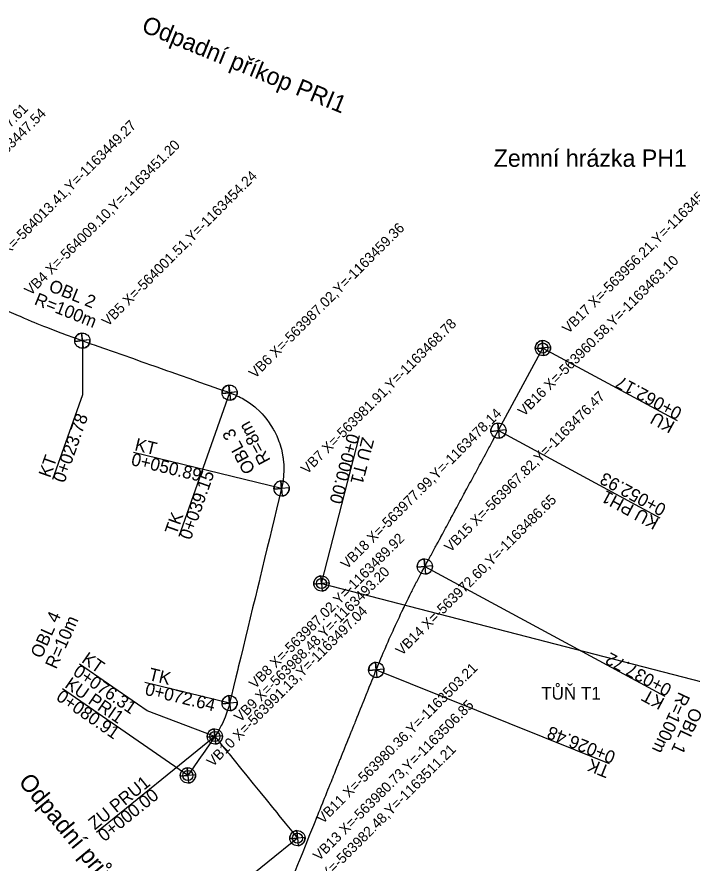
# Model space of a CAD drawing. Extents: x -564052 to -563798, y -1163587 to -1163361.
# Drawn here: x -564007.9 to -563941.5, y -1163505.7 to -1163422.4 of the extents above; entities that cross this region are included whole.
import ezdxf

# ---------------------------------------------------------------- set-up
doc = ezdxf.new("R2010")
doc.units = 0
for name, color, linetype in [('4', 7, 'Continuous'), ('5', 7, 'Continuous'), ('_popis staničení PH1', 7, 'Continuous'), ('_popis staničení PRI1', 7, 'Continuous'), ('_popis staničení PRU1', 7, 'Continuous'), ('_popis staničení T1', 7, 'Continuous'), ('_rám C35', 7, 'Continuous'), ('Default', 7, 'Continuous')]:
    doc.layers.add(name, color=color, linetype=linetype)

msp = doc.modelspace()

# ---------------------------------------------------------------- linework, layer by layer
for points in [[(-564008.737, -1163451.365), (-564007.821, -1163451.766), (-564007.636, -1163451.846), (-564007.226, -1163452.021), (-564006.901, -1163452.158), (-564006.468, -1163452.339), (-564006.293, -1163452.411), (-564005.977, -1163452.541), (-564005.335, -1163452.8), (-564005.049, -1163452.914), (-564004.118, -1163453.278), (-564004.036, -1163453.31), (-564003.622, -1163453.468), (-564003.43, -1163453.54), (-564003.183, -1163453.633), (-564002.245, -1163453.978), (-564001.885, -1163454.108), (-564001.714, -1163454.169), (-564001.509, -1163454.241), (-564001.303, -1163454.314), (-564000.564, -1163454.575), (-564000.36, -1163454.647), (-563999.417, -1163454.981), (-563998.474, -1163455.314), (-563997.531, -1163455.647), (-563996.589, -1163455.98), (-563995.646, -1163456.314), (-563995.452, -1163456.382), (-563995.448, -1163456.384), (-563994.703, -1163456.647), (-563994.566, -1163456.696), (-563994.476, -1163456.727), (-563994.186, -1163456.83), (-563993.76, -1163456.98), (-563993.219, -1163457.172), (-563992.817, -1163457.314), (-563991.874, -1163457.647), (-563990.932, -1163457.98), (-563989.989, -1163458.313), (-563989.326, -1163458.548), (-563989.046, -1163458.647), (-563988.103, -1163458.98), (-563987.622, -1163459.15), (-563987.311, -1163459.26), (-563987.16, -1163459.313), (-563987.022, -1163459.362), (-563986.743, -1163459.467), (-563986.664, -1163459.498), (-563986.631, -1163459.512), (-563986.476, -1163459.578), (-563986.234, -1163459.689), (-563986.126, -1163459.742), (-563985.948, -1163459.833), (-563985.802, -1163459.912), (-563985.439, -1163460.127), (-563985.361, -1163460.176), (-563984.953, -1163460.456), (-563984.556, -1163460.768), (-563984.493, -1163460.821), (-563984.061, -1163461.219), (-563983.898, -1163461.385), (-563983.831, -1163461.455), (-563983.659, -1163461.647), (-563983.474, -1163461.866), (-563983.29, -1163462.103), (-563983.198, -1163462.228), (-563982.955, -1163462.585), (-563982.734, -1163462.951), (-563982.73, -1163462.956), (-563982.717, -1163462.98), (-563982.665, -1163463.074), (-563982.656, -1163463.091), (-563982.395, -1163463.617), (-563982.242, -1163463.979), (-563982.174, -1163464.161), (-563982.101, -1163464.367), (-563982.092, -1163464.395), (-563982.032, -1163464.585), (-563982.015, -1163464.641), (-563981.993, -1163464.719), (-563981.936, -1163464.931), (-563981.853, -1163465.29), (-563981.78, -1163465.696), (-563981.763, -1163465.812), (-563981.756, -1163465.869), (-563981.75, -1163465.912), (-563981.701, -1163466.453), (-563981.688, -1163466.91), (-563981.69, -1163467.04), (-563981.708, -1163467.467), (-563981.721, -1163467.627), (-563981.751, -1163467.907), (-563981.795, -1163468.209), (-563981.912, -1163468.784), (-563981.938, -1163468.889), (-563982.011, -1163469.191), (-563982.173, -1163469.861), (-563982.408, -1163470.833), (-563982.643, -1163471.805), (-563982.878, -1163472.777), (-563983.113, -1163473.749), (-563983.348, -1163474.721), (-563983.583, -1163475.693), (-563983.818, -1163476.665), (-563984.052, -1163477.637), (-563984.101, -1163477.836), (-563984.287, -1163478.609), (-563984.522, -1163479.581), (-563984.757, -1163480.553), (-563984.992, -1163481.525), (-563985.227, -1163482.497), (-563985.462, -1163483.469), (-563985.697, -1163484.441), (-563985.932, -1163485.413), (-563986.167, -1163486.385), (-563986.222, -1163486.612), (-563986.402, -1163487.357), (-563986.637, -1163488.329), (-563986.872, -1163489.301), (-563987.022, -1163489.919), (-563987.114, -1163490.272), (-563987.22, -1163490.627), (-563987.431, -1163491.219), (-563987.47, -1163491.317), (-563987.771, -1163491.988), (-563987.842, -1163492.131), (-563988.119, -1163492.635), (-563988.342, -1163492.996), (-563988.514, -1163493.254), (-563988.906, -1163493.822), (-563989.475, -1163494.644), (-563990.043, -1163495.467), (-563990.612, -1163496.29), (-563991.13, -1163497.04)], [(-563980.618, -1163506.572), (-563980.244, -1163505.644), (-563980.216, -1163505.574), (-563979.871, -1163504.716), (-563979.497, -1163503.789), (-563979.124, -1163502.861), (-563978.751, -1163501.933), (-563978.377, -1163501.006), (-563978.349, -1163500.935), (-563978.237, -1163500.657), (-563978.236, -1163500.655), (-563978.125, -1163500.38), (-563978.015, -1163500.104), (-563978.004, -1163500.078), (-563977.904, -1163499.829), (-563977.793, -1163499.554), (-563977.682, -1163499.279), (-563977.631, -1163499.15), (-563977.571, -1163499.003), (-563977.461, -1163498.728), (-563977.35, -1163498.453), (-563977.257, -1163498.223), (-563977.239, -1163498.177), (-563977.128, -1163497.902), (-563977.017, -1163497.627), (-563976.907, -1163497.351), (-563976.884, -1163497.295), (-563976.796, -1163497.076), (-563976.685, -1163496.801), (-563976.574, -1163496.525), (-563976.511, -1163496.367), (-563976.463, -1163496.25), (-563976.353, -1163495.975), (-563976.242, -1163495.699), (-563976.137, -1163495.44), (-563976.131, -1163495.424), (-563976.02, -1163495.149), (-563975.909, -1163494.873), (-563975.798, -1163494.598), (-563975.764, -1163494.512), (-563975.688, -1163494.323), (-563975.577, -1163494.047), (-563975.466, -1163493.772), (-563975.39, -1163493.584), (-563975.355, -1163493.497), (-563975.244, -1163493.221), (-563975.134, -1163492.946), (-563975.023, -1163492.671), (-563975.017, -1163492.657), (-563974.912, -1163492.395), (-563974.801, -1163492.12), (-563974.69, -1163491.845), (-563974.644, -1163491.729), (-563974.58, -1163491.569), (-563974.469, -1163491.294), (-563974.358, -1163491.019), (-563974.27, -1163490.801), (-563974.247, -1163490.744), (-563974.136, -1163490.468), (-563974.025, -1163490.193), (-563973.915, -1163489.918), (-563973.897, -1163489.873), (-563973.804, -1163489.642), (-563973.693, -1163489.367), (-563973.582, -1163489.092), (-563973.524, -1163488.946), (-563973.471, -1163488.816), (-563973.361, -1163488.541), (-563973.25, -1163488.266), (-563973.15, -1163488.018), (-563973.139, -1163487.99), (-563973.028, -1163487.715), (-563972.917, -1163487.44), (-563972.807, -1163487.164), (-563972.777, -1163487.09), (-563972.696, -1163486.889), (-563972.599, -1163486.649), (-563972.585, -1163486.614), (-563972.474, -1163486.339), (-563972.402, -1163486.163), (-563972.361, -1163486.064), (-563972.249, -1163485.789), (-563972.135, -1163485.515), (-563972.02, -1163485.241), (-563972.019, -1163485.239), (-563971.905, -1163484.968), (-563971.789, -1163484.695), (-563971.736, -1163484.572), (-563971.672, -1163484.422), (-563971.627, -1163484.32), (-563971.554, -1163484.15), (-563971.435, -1163483.878), (-563971.316, -1163483.606), (-563971.226, -1163483.404), (-563971.195, -1163483.335), (-563971.074, -1163483.064), (-563970.952, -1163482.793), (-563970.83, -1163482.523), (-563970.826, -1163482.515), (-563970.816, -1163482.492), (-563970.706, -1163482.253), (-563970.582, -1163481.983), (-563970.457, -1163481.714), (-563970.396, -1163481.584), (-563970.331, -1163481.446), (-563970.205, -1163481.177), (-563970.077, -1163480.909), (-563969.968, -1163480.68), (-563969.949, -1163480.641), (-563969.87, -1163480.479), (-563969.82, -1163480.374), (-563969.69, -1163480.107), (-563969.559, -1163479.841), (-563969.53, -1163479.781), (-563969.428, -1163479.575), (-563969.296, -1163479.309), (-563969.163, -1163479.044), (-563969.084, -1163478.886), (-563969.029, -1163478.779), (-563968.894, -1163478.514), (-563968.869, -1163478.464), (-563968.759, -1163478.25), (-563968.628, -1163477.996), (-563968.623, -1163477.986), (-563968.486, -1163477.723), (-563968.348, -1163477.46), (-563968.21, -1163477.198), (-563968.164, -1163477.111), (-563968.071, -1163476.936), (-563967.931, -1163476.674), (-563967.823, -1163476.473), (-563967.79, -1163476.413), (-563967.691, -1163476.229), (-563967.649, -1163476.151), (-563967.508, -1163475.89), (-563967.367, -1163475.629), (-563967.226, -1163475.368), (-563967.216, -1163475.349), (-563967.085, -1163475.107), (-563966.944, -1163474.846), (-563966.803, -1163474.585), (-563966.741, -1163474.47), (-563966.662, -1163474.323), (-563966.521, -1163474.062), (-563966.38, -1163473.801), (-563966.265, -1163473.59), (-563966.239, -1163473.54), (-563966.098, -1163473.279), (-563965.957, -1163473.018), (-563965.816, -1163472.757), (-563965.79, -1163472.71), (-563965.675, -1163472.495), (-563965.534, -1163472.234), (-563965.393, -1163471.973), (-563965.315, -1163471.83), (-563965.252, -1163471.712), (-563965.111, -1163471.451), (-563964.97, -1163471.19), (-563964.84, -1163470.95), (-563964.829, -1163470.929), (-563964.688, -1163470.667), (-563964.547, -1163470.406), (-563964.406, -1163470.145), (-563964.365, -1163470.07), (-563964.265, -1163469.884), (-563964.123, -1163469.623), (-563963.982, -1163469.362), (-563963.89, -1163469.19), (-563963.841, -1163469.1), (-563963.7, -1163468.839), (-563963.559, -1163468.578), (-563963.418, -1163468.317), (-563963.415, -1163468.31), (-563963.277, -1163468.056), (-563963.136, -1163467.795), (-563962.995, -1163467.534), (-563962.94, -1163467.43), (-563962.854, -1163467.272), (-563962.713, -1163467.011), (-563962.572, -1163466.75), (-563962.464, -1163466.55), (-563962.431, -1163466.489), (-563962.29, -1163466.228), (-563962.149, -1163465.967), (-563962.008, -1163465.706), (-563961.989, -1163465.67), (-563961.867, -1163465.444), (-563961.726, -1163465.183), (-563961.585, -1163464.922), (-563961.514, -1163464.79), (-563961.444, -1163464.661), (-563961.303, -1163464.4), (-563961.162, -1163464.139), (-563961.039, -1163463.911), (-563961.021, -1163463.878), (-563960.88, -1163463.616), (-563960.739, -1163463.355), (-563956.21, -1163454.967), (-563956.209, -1163454.966)], [(-563988.478, -1163493.203), (-563987.986, -1163493.809), (-563987.848, -1163493.98), (-563987.218, -1163494.756), (-563987.081, -1163494.925), (-563986.588, -1163495.533), (-563985.957, -1163496.309), (-563985.327, -1163497.086), (-563984.697, -1163497.863), (-563984.067, -1163498.639), (-563983.437, -1163499.416), (-563982.807, -1163500.192), (-563982.395, -1163500.7), (-563982.177, -1163500.969), (-563981.547, -1163501.745), (-563980.917, -1163502.522), (-563980.358, -1163503.212)]]:
    msp.add_lwpolyline(points)
at = {"layer": '5'}
msp.add_line((-563977.993, -1163478.142), (-563940.586, -1163487.812), dxfattribs=at)
at = {"layer": '_popis staničení PH1'}
for points in [[(-563956.209, -1163454.966), (-563943.01, -1163462.093)], [(-563960.584, -1163463.099), (-563944.707, -1163471.673)], [(-563967.823, -1163476.473), (-563944.204, -1163489.227)], [(-563972.599, -1163486.649), (-563949.695, -1163495.868)]]:
    msp.add_lwpolyline(points, dxfattribs=at)
msp.add_circle((-563956.209, -1163454.966), 0.5, dxfattribs=at)
at = {"layer": '_popis staničení PRI1'}
for points in [[(-564001.509, -1163454.241), (-564001.502, -1163459.568), (-564004.444, -1163467.892)], [(-563987.022, -1163459.362), (-563992.021, -1163473.504)], [(-563981.912, -1163468.784), (-563996.492, -1163465.26)], [(-563988.478, -1163493.203), (-563995.124, -1163490.664), (-564001.8, -1163486.071)], [(-563991.13, -1163497.04), (-564003.471, -1163488.514)], [(-563987.022, -1163489.919), (-563995.349, -1163487.906)]]:
    msp.add_lwpolyline(points, dxfattribs=at)
msp.add_circle((-563991.13, -1163497.04), 0.5, dxfattribs=at)
at = {"layer": '_popis staničení PRU1'}
for points in [[(-563988.478, -1163493.203), (-564000.126, -1163502.654)], [(-563980.358, -1163503.212), (-563992.006, -1163512.662)]]:
    msp.add_lwpolyline(points, dxfattribs=at)
for centre in [(-563988.478, -1163493.203), (-563980.358, -1163503.212)]:
    msp.add_circle(centre, 0.5, dxfattribs=at)
at = {"layer": '_popis staničení T1'}
msp.add_lwpolyline([(-563977.993, -1163478.142), (-563974.239, -1163463.619)], dxfattribs=at)
msp.add_circle((-563977.993, -1163478.142), 0.5, dxfattribs=at)
at = {"layer": '_rám C35'}
for p, q in [((-564001.509, -1163454.241), (-564001.579, -1163453.494)), ((-564001.509, -1163454.241), (-564001.579, -1163453.494)), ((-564001.578, -1163453.495), (-564001.44, -1163454.988)), ((-564000.762, -1163454.172), (-564002.256, -1163454.311)), ((-564002.256, -1163454.311), (-564001.509, -1163454.241)), ((-564002.256, -1163454.311), (-564001.509, -1163454.241)), ((-564000.762, -1163454.172), (-564001.509, -1163454.241)), ((-564001.509, -1163454.241), (-564001.439, -1163454.988)), ((-563956.209, -1163454.966), (-563956.279, -1163454.218)), ((-563956.209, -1163454.966), (-563956.279, -1163454.218)), ((-563956.278, -1163454.219), (-563956.14, -1163455.712)), ((-563955.462, -1163454.896), (-563956.956, -1163455.035)), ((-563956.956, -1163455.035), (-563956.209, -1163454.966)), ((-563956.956, -1163455.035), (-563956.209, -1163454.966)), ((-563955.462, -1163454.896), (-563956.209, -1163454.966)), ((-563956.209, -1163454.966), (-563956.139, -1163455.713)), ((-563986.276, -1163459.292), (-563987.769, -1163459.431)), ((-563987.769, -1163459.431), (-563987.022, -1163459.362)), ((-563987.769, -1163459.431), (-563987.022, -1163459.362)), ((-563987.092, -1163458.615), (-563986.953, -1163460.109)), ((-563987.022, -1163459.362), (-563987.092, -1163458.615)), ((-563987.022, -1163459.362), (-563987.092, -1163458.615)), ((-563986.275, -1163459.292), (-563987.022, -1163459.362)), ((-563987.022, -1163459.362), (-563986.953, -1163460.109)), ((-563960.584, -1163463.099), (-563960.654, -1163462.352)), ((-563960.584, -1163463.099), (-563960.654, -1163462.352)), ((-563960.654, -1163462.353), (-563960.515, -1163463.846)), ((-563961.332, -1163463.169), (-563960.584, -1163463.099)), ((-563961.332, -1163463.169), (-563960.584, -1163463.099)), ((-563959.838, -1163463.03), (-563961.331, -1163463.169)), ((-563959.837, -1163463.03), (-563960.584, -1163463.099)), ((-563960.584, -1163463.099), (-563960.515, -1163463.847)), ((-563981.912, -1163468.784), (-563981.982, -1163468.037)), ((-563981.912, -1163468.784), (-563981.982, -1163468.037)), ((-563981.982, -1163468.038), (-563981.843, -1163469.531)), ((-563982.66, -1163468.854), (-563981.912, -1163468.784)), ((-563981.166, -1163468.715), (-563982.659, -1163468.854)), ((-563982.659, -1163468.854), (-563981.912, -1163468.784)), ((-563981.165, -1163468.715), (-563981.912, -1163468.784)), ((-563981.912, -1163468.784), (-563981.843, -1163469.531)), ((-563967.823, -1163476.473), (-563967.892, -1163475.726)), ((-563967.823, -1163476.473), (-563967.892, -1163475.726)), ((-563967.892, -1163475.727), (-563967.753, -1163477.22)), ((-563968.57, -1163476.543), (-563967.823, -1163476.473)), ((-563968.57, -1163476.543), (-563967.823, -1163476.473)), ((-563967.076, -1163476.404), (-563968.569, -1163476.543)), ((-563967.075, -1163476.404), (-563967.823, -1163476.473)), ((-563967.823, -1163476.473), (-563967.753, -1163477.22)), ((-563978.063, -1163477.395), (-563977.924, -1163478.889)), ((-563977.993, -1163478.142), (-563978.063, -1163477.395)), ((-563977.993, -1163478.142), (-563978.063, -1163477.395)), ((-563977.246, -1163478.073), (-563978.74, -1163478.212)), ((-563978.74, -1163478.212), (-563977.993, -1163478.142)), ((-563978.74, -1163478.212), (-563977.993, -1163478.142)), ((-563977.246, -1163478.073), (-563977.993, -1163478.142)), ((-563977.993, -1163478.142), (-563977.923, -1163478.889)), ((-563972.599, -1163486.649), (-563972.669, -1163485.902)), ((-563972.599, -1163486.649), (-563972.669, -1163485.902)), ((-563972.669, -1163485.903), (-563972.53, -1163487.396)), ((-563971.853, -1163486.58), (-563973.346, -1163486.719)), ((-563973.346, -1163486.719), (-563972.599, -1163486.649)), ((-563973.346, -1163486.719), (-563972.599, -1163486.649)), ((-563971.852, -1163486.58), (-563972.599, -1163486.649)), ((-563972.599, -1163486.649), (-563972.53, -1163487.396)), ((-563987.022, -1163489.919), (-563987.091, -1163489.172)), ((-563987.022, -1163489.919), (-563987.091, -1163489.172)), ((-563987.091, -1163489.173), (-563986.952, -1163490.666)), ((-563987.769, -1163489.989), (-563987.022, -1163489.919)), ((-563987.769, -1163489.989), (-563987.022, -1163489.919)), ((-563986.275, -1163489.85), (-563987.768, -1163489.989)), ((-563986.274, -1163489.85), (-563987.022, -1163489.919)), ((-563987.022, -1163489.919), (-563986.952, -1163490.667)), ((-563988.478, -1163493.203), (-563988.547, -1163492.456)), ((-563988.478, -1163493.203), (-563988.547, -1163492.456)), ((-563988.547, -1163492.457), (-563988.408, -1163493.95)), ((-563989.225, -1163493.273), (-563988.478, -1163493.203)), ((-563989.225, -1163493.273), (-563988.478, -1163493.203)), ((-563987.731, -1163493.134), (-563989.224, -1163493.273)), ((-563987.73, -1163493.134), (-563988.478, -1163493.203)), ((-563988.478, -1163493.203), (-563988.408, -1163493.95)), ((-563991.13, -1163497.04), (-563991.2, -1163496.293)), ((-563991.13, -1163497.04), (-563991.2, -1163496.293)), ((-563991.199, -1163496.293), (-563991.061, -1163497.787)), ((-563990.383, -1163496.971), (-563991.877, -1163497.109)), ((-563991.877, -1163497.11), (-563991.13, -1163497.04)), ((-563991.877, -1163497.109), (-563991.13, -1163497.04)), ((-563990.383, -1163496.97), (-563991.13, -1163497.04)), ((-563991.13, -1163497.04), (-563991.06, -1163497.787)), ((-563980.358, -1163503.212), (-563980.427, -1163502.464)), ((-563980.358, -1163503.212), (-563980.427, -1163502.464)), ((-563980.427, -1163502.465), (-563980.288, -1163503.958)), ((-563981.105, -1163503.281), (-563980.358, -1163503.212)), ((-563981.105, -1163503.281), (-563980.358, -1163503.212)), ((-563979.611, -1163503.142), (-563981.104, -1163503.281)), ((-563979.611, -1163503.142), (-563980.358, -1163503.212)), ((-563980.358, -1163503.212), (-563980.288, -1163503.959))]:
    msp.add_line(p, q, dxfattribs=at)
for centre in [(-564001.509, -1163454.241), (-563956.209, -1163454.966), (-563987.022, -1163459.362), (-563960.584, -1163463.099), (-563981.912, -1163468.784), (-563967.823, -1163476.473), (-563977.993, -1163478.142), (-563972.599, -1163486.649), (-563987.022, -1163489.919), (-563988.478, -1163493.203), (-563991.13, -1163497.04), (-563980.358, -1163503.212)]:
    msp.add_circle(centre, 0.75, dxfattribs=at)
for centre, start, end in [((-564001.509, -1163454.241), 95.31679, 185.31679), ((-564001.509, -1163454.241), 95.31679, 185.31679), ((-564001.509, -1163454.241), 275.31679, 5.31679), ((-563956.209, -1163454.966), 95.31679, 185.31679), ((-563956.209, -1163454.966), 95.31679, 185.31679), ((-563956.209, -1163454.966), 275.31679, 5.31679), ((-563987.022, -1163459.362), 95.31679, 185.31679), ((-563987.022, -1163459.362), 95.31679, 185.31679), ((-563987.022, -1163459.362), 275.31679, 5.31679), ((-563960.584, -1163463.099), 95.31679, 185.31679), ((-563960.584, -1163463.099), 95.31679, 185.31679), ((-563960.584, -1163463.099), 275.31679, 5.31679), ((-563981.912, -1163468.784), 95.31679, 185.31679), ((-563981.912, -1163468.784), 95.31679, 185.31679), ((-563981.912, -1163468.784), 275.31679, 5.31679), ((-563967.823, -1163476.473), 95.31679, 185.31679), ((-563967.823, -1163476.473), 95.31679, 185.31679), ((-563967.823, -1163476.473), 275.31679, 5.31679), ((-563977.993, -1163478.142), 95.31679, 185.31679), ((-563977.993, -1163478.142), 95.31679, 185.31679), ((-563977.993, -1163478.142), 275.31679, 5.31679), ((-563972.599, -1163486.649), 95.31679, 185.31679), ((-563972.599, -1163486.649), 95.31679, 185.31679), ((-563972.599, -1163486.649), 275.31679, 5.31679), ((-563987.022, -1163489.919), 95.31679, 185.31679), ((-563987.022, -1163489.919), 95.31679, 185.31679), ((-563987.022, -1163489.919), 275.31679, 5.31679), ((-563988.478, -1163493.203), 95.31679, 185.31679), ((-563988.478, -1163493.203), 95.31679, 185.31679), ((-563988.478, -1163493.203), 275.31679, 5.31679), ((-563991.13, -1163497.04), 95.31679, 185.31679), ((-563991.13, -1163497.04), 95.31679, 185.31679), ((-563991.13, -1163497.04), 275.31679, 5.31679), ((-563980.358, -1163503.212), 95.31679, 185.31679), ((-563980.358, -1163503.212), 95.31679, 185.31679), ((-563980.358, -1163503.212), 275.31679, 5.31679)]:
    msp.add_arc(centre, 0.75, start, end, dxfattribs=at)

# ---------------------------------------------------------------- texts
at = {"layer": '4'}
for s, height, rotation, p in [('Odpadní příkop PRI1', 1.70472, 337.7031, (-563995.793, -1163423.777)), ('Zemní hrázka PH1', 1.70472, 360, (-563961.048, -1163437.127)), ('TŮŇ T1', 1.25, 360, (-563956.376, -1163489.573)), ('Odpadní průleh PRU1', 1.70472, 309.48875, (-564007.868, -1163497.695))]:
    msp.add_text(s, height=height, rotation=rotation, dxfattribs=at).set_placement(p)
at = {"layer": '_popis staničení PH1'}
for s, rotation, p in [('0+062.17', 151.63216, (-563942.416, -1163460.993)), ('KU ', 151.63216, (-563943.129, -1163462.313)), ('0+052.93', 151.63216, (-563943.971, -1163470.48)), ('KU PH1 ', 151.63216, (-563944.684, -1163471.8)), ('0+037.72', 151.63216, (-563943.427, -1163488.211)), ('KT ', 151.63216, (-563944.14, -1163489.531)), ('R=100m ', 244.85429, (-563942.815, -1163488.741)), ('OBL 1', 244.85429, (-563941.595, -1163490.259)), ('0+026.48', 158.07641, (-563948.961, -1163494.771)), ('TK ', 158.07641, (-563949.521, -1163496.163))]:
    msp.add_text(s, height=1.25, rotation=rotation, dxfattribs=at).set_placement(p)
at = {"layer": '_popis staničení PRI1'}
for s, rotation, p in [('OBL 2', 338.1901, (-564004.911, -1163449.325)), ('R=100m ', 338.1901, (-564006.322, -1163450.645)), ('0+023.78', 70.53291, (-564003.265, -1163468.309)), ('R=8m ', 118.47147, (-563982.968, -1163466.015)), ('OBL 3', 118.47147, (-563984.452, -1163466.949)), ('KT ', 346.41002, (-563996.434, -1163465.017)), ('KT ', 70.53291, (-564004.68, -1163467.809)), ('0+050.89', 346.41002, (-563996.786, -1163466.475)), ('0+039.15', 70.53291, (-563990.843, -1163473.921)), ('TK ', 70.53291, (-563992.257, -1163473.421)), ('OBL 4', 65.88483, (-564005.524, -1163485.591)), ('R=10m ', 65.88483, (-564004.078, -1163486.644)), ('KT ', 325.35964, (-564001.665, -1163485.838)), ('0+076.31', 325.35964, (-564002.518, -1163487.073)), ('TK ', 346.41002, (-563995.073, -1163487.636)), ('KU PRI1 ', 325.35964, (-564003.329, -1163488.308)), ('0+072.64', 346.41002, (-563995.426, -1163489.094)), ('0+080.91', 325.35964, (-564004.182, -1163489.542))]:
    msp.add_text(s, height=1.25, rotation=rotation, dxfattribs=at).set_placement(p)
at = {"layer": '_popis staničení PRU1'}
for s, p in [('ZU PRU1 ', (-564000.284, -1163502.46)), ('0+000.00', (-563999.339, -1163503.624))]:
    msp.add_text(s, height=1.25, rotation=39.05251, dxfattribs=at).set_placement(p)
at = {"layer": '_popis staničení T1'}
for s, p in [('0+000.00', (-563975.449, -1163463.307)), ('ZU T1 ', (-563973.997, -1163463.682))]:
    msp.add_text(s, height=1.25, rotation=255.5058, dxfattribs=at).set_placement(p)
at = {"layer": 'Default'}
for s, p in [('VB1 X=-564024.04,Y=-1163447.61', (-564021.54, -1163446.262)), ('VB2 X=-564022.49,Y=-1163447.54', (-564019.779, -1163446.729)), ('VB3 X=-564013.41,Y=-1163449.27', (-564010.91, -1163447.923)), ('VB4 X=-564009.10,Y=-1163451.20', (-564006.6, -1163449.856)), ('VB5 X=-564001.51,Y=-1163454.24', (-563999.009, -1163452.893)), ('VB17 X=-563956.21,Y=-1163454.97', (-563953.709, -1163453.617)), ('VB6 X=-563987.02,Y=-1163459.36', (-563984.523, -1163458.014)), ('VB16 X=-563960.58,Y=-1163463.10', (-563958.085, -1163461.751)), ('VB7 X=-563981.91,Y=-1163468.78', (-563979.413, -1163467.436)), ('VB15 X=-563967.82,Y=-1163476.47', (-563965.323, -1163475.125)), ('VB18 X=-563977.99,Y=-1163478.14', (-563975.493, -1163476.794)), ('VB14 X=-563972.60,Y=-1163486.65', (-563970.1, -1163485.301)), ('VB8 X=-563987.02,Y=-1163489.92', (-563984.522, -1163488.571)), ('VB9 X=-563988.48,Y=-1163493.20', (-563985.978, -1163491.855)), ('VB10 X=-563991.13,Y=-1163497.04', (-563988.692, -1163496.249)), ('VB11 X=-563980.36,Y=-1163503.21', (-563977.858, -1163501.863)), ('VB13 X=-563980.73,Y=-1163506.85', (-563978.23, -1163505.502)), ('VB12 X=-563982.48,Y=-1163511.21', (-563979.985, -1163509.862))]:
    msp.add_text(s, height=1, rotation=45, dxfattribs=at).set_placement(p)

doc.saveas('drawing.dxf')
